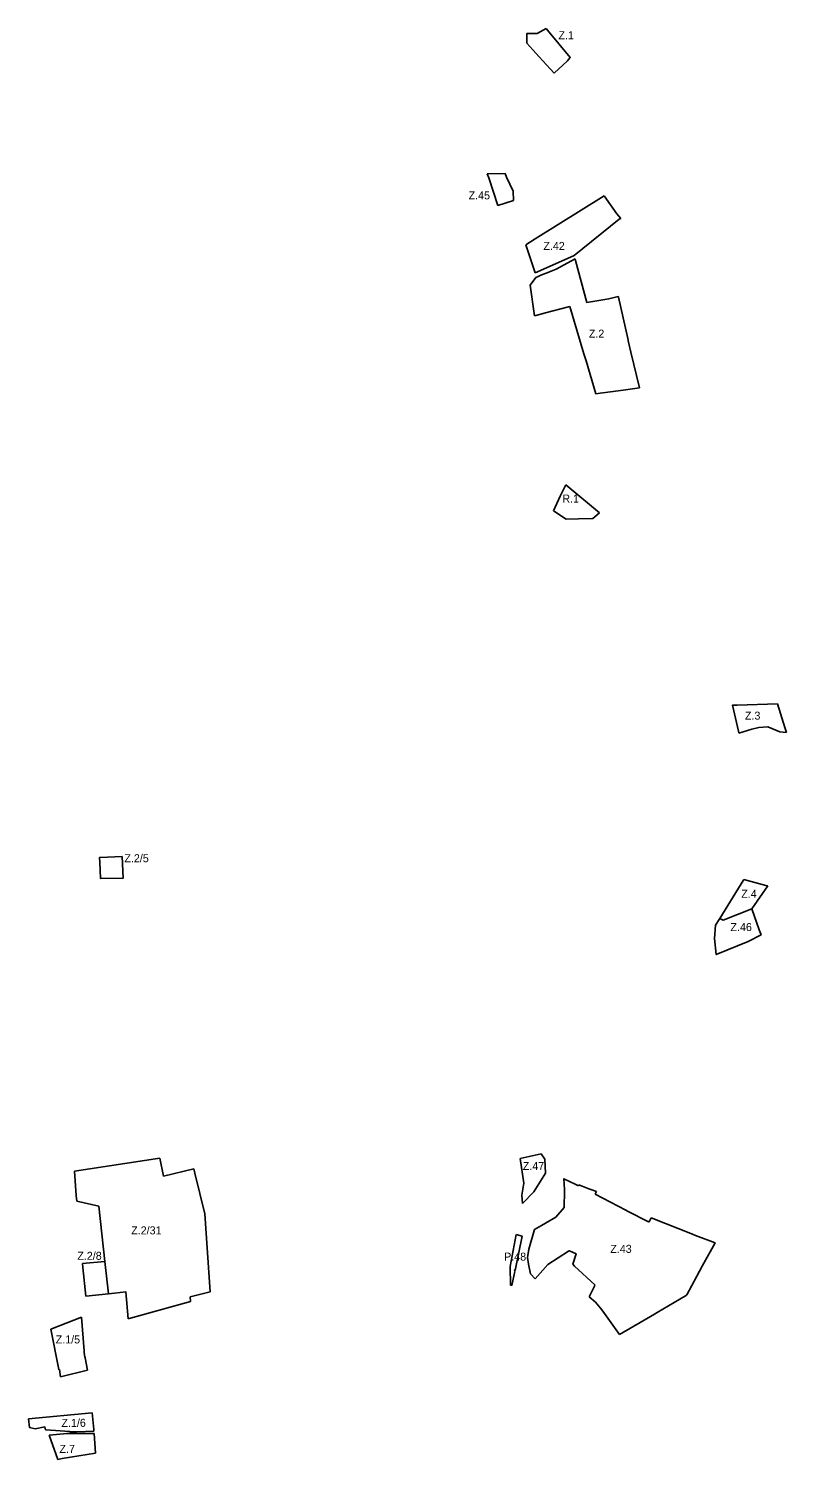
# Model space of a CAD drawing. Extents: x -438701 to -435614, y -1126017 to -1121766.
# Drawn here: x -438045 to -437098, y -1123554 to -1121766 of the extents above; entities that cross this region are included whole.
import ezdxf

# ---------------------------------------------------------------- set-up
doc = ezdxf.new("R2010")
doc.units = 0
for name, color, linetype in [('NAVRH', 7, 'Continuous'), ('STAV', 7, 'Continuous'), ('Vrstva 12', 7, 'Continuous'), ('Vrstva 13', 7, 'Continuous'), ('Vrstva 3', 7, 'Continuous'), ('Vrstva 5', 7, 'Continuous'), ('Vrstva 6', 7, 'Continuous'), ('Vrstva 7', 7, 'Continuous'), ('Vrstva 9', 7, 'Continuous')]:
    doc.layers.add(name, color=color, linetype=linetype)

msp = doc.modelspace()

# ---------------------------------------------------------------- linework, layer by layer
at = {"layer": 'NAVRH'}
for p, q in [((-437396.6, -1121767.7), (-437398, -1121765.9)), ((-437414.7, -1121792.6), (-437406.9, -1121801.2)), ((-437406.9, -1121801.2), (-437393.3, -1121816.2)), ((-437388.2, -1121821.8), (-437371.6, -1121806.2)), ((-437371.6, -1121806.2), (-437370.3, -1121804.6)), ((-437393.3, -1121816.2), (-437388.2, -1121821.8)), ((-437449.6, -1121947), (-437471.7, -1121947.3)), ((-437471.7, -1121947.3), (-437470, -1121952.2)), ((-437447.7, -1121951.4), (-437449.6, -1121947)), ((-437439.6, -1121969), (-437447.7, -1121951.4)), ((-437439.1, -1121980.9), (-437439.6, -1121969)), ((-437325.7, -1121974.7), (-437411.8, -1122028.6)), ((-437310, -1121997.2), (-437325.7, -1121974.7)), ((-437363.3, -1122049.6), (-437306.8, -1122004.2)), ((-437305, -1122003.2), (-437310, -1121997.2)), ((-437306.8, -1122004.2), (-437305, -1122003.2)), ((-437411.8, -1122028.6), (-437423.7, -1122036.3)), ((-437423.7, -1122036.3), (-437411.9, -1122071)), ((-437409.1, -1122069.8), (-437363.3, -1122049.6)), ((-437362, -1122053.5), (-437385.7, -1122066.5)), ((-437361.4, -1122055.6), (-437362, -1122053.5)), ((-437347.6, -1122108), (-437361.4, -1122055.6)), ((-437411.3, -1122077), (-437418, -1122086.6)), ((-437411.9, -1122071), (-437409.1, -1122069.8)), ((-437409.1, -1122076), (-437411.3, -1122077)), ((-437404.8, -1122074), (-437409.1, -1122076)), ((-437418, -1122086.6), (-437412.6, -1122124.7)), ((-437400.6, -1122121.5), (-437368.7, -1122113)), ((-437368.7, -1122113), (-437351, -1122172.5)), ((-437320, -1122103.7), (-437347.6, -1122108)), ((-437308.1, -1122100.5), (-437320, -1122103.7)), ((-437307.8, -1122101.4), (-437308.1, -1122100.5)), ((-437296.3, -1122153.1), (-437307.8, -1122101.4)), ((-437412.6, -1122124.7), (-437404.9, -1122122.6)), ((-437404.9, -1122122.6), (-437400.6, -1122121.5)), ((-437295.3, -1122157.7), (-437296.3, -1122153.1)), ((-437292.4, -1122170.4), (-437295.3, -1122157.7)), ((-437281.8, -1122215), (-437292.4, -1122170.4)), ((-437351, -1122172.5), (-437349.6, -1122177.3)), ((-437349.6, -1122177.3), (-437348.4, -1122181.1)), ((-437348.4, -1122181.1), (-437336.1, -1122222.1)), ((-437336.1, -1122222.1), (-437330.8, -1122221.4)), ((-437330.8, -1122221.4), (-437314.6, -1122219.3)), ((-437314.6, -1122219.3), (-437298.9, -1122217.2)), ((-437298.9, -1122217.2), (-437284.7, -1122215.3)), ((-437284.7, -1122215.3), (-437281.8, -1122215)), ((-437109.4, -1122609.8), (-437159.8, -1122611.3)), ((-437099.9, -1122639.3), (-437109.4, -1122609.8)), ((-437158, -1122643.9), (-437157.4, -1122646.2)), ((-437157.4, -1122646.2), (-437141.4, -1122641.3)), ((-437141.4, -1122641.3), (-437132.5, -1122639.1)), ((-437132.5, -1122639.1), (-437121.2, -1122638.5)), ((-437121.2, -1122638.5), (-437106.1, -1122644.8)), ((-437106.1, -1122644.8), (-437098.1, -1122645.4)), ((-437098.1, -1122645.4), (-437099.9, -1122639.3)), ((-437151.1, -1122829.1), (-437181.3, -1122877.7)), ((-437123.7, -1122836.8), (-437151.1, -1122829.1)), ((-437141.4, -1122865.8), (-437121.4, -1122837.2)), ((-437121.4, -1122837.2), (-437123.7, -1122836.8)), ((-437132, -1122892.2), (-437141.4, -1122865.8)), ((-437181.3, -1122877.7), (-437186.6, -1122886.2)), ((-437404.3, -1123171.9), (-437430.5, -1123177.6)), ((-437399.7, -1123178.7), (-437404.3, -1123171.9)), ((-437881, -1123177.2), (-437987.6, -1123193.6)), ((-437876.1, -1123200), (-437881, -1123177.2)), ((-437430.5, -1123177.6), (-437426, -1123208.7)), ((-437399, -1123196.1), (-437399.7, -1123178.7)), ((-437987.6, -1123193.6), (-437985.2, -1123224.1)), ((-437838.2, -1123190.7), (-437876.1, -1123200)), ((-437836.9, -1123196.1), (-437838.2, -1123190.7)), ((-437824.4, -1123247.1), (-437836.9, -1123196.1)), ((-437985.2, -1123224.1), (-437984.6, -1123231)), ((-437426, -1123208.7), (-437428.8, -1123223.5)), ((-437428.8, -1123223.5), (-437427.9, -1123234.2)), ((-437375.1, -1123218.2), (-437375.7, -1123239)), ((-437375.2, -1123216.8), (-437375.1, -1123218.2)), ((-437357.9, -1123212), (-437361.9, -1123210)), ((-437357.5, -1123210.9), (-437357.9, -1123212)), ((-437335.4, -1123219.1), (-437342.2, -1123216.6)), ((-437336.8, -1123222.5), (-437335.4, -1123219.1)), ((-437298.6, -1123242.4), (-437336.8, -1123222.5)), ((-437984.6, -1123231), (-437957.1, -1123237.3)), ((-437957.1, -1123237.3), (-437949.6, -1123306.5)), ((-437375.7, -1123239), (-437386.1, -1123251.2)), ((-437296.7, -1123243.4), (-437298.6, -1123242.4)), ((-437398.9, -1123258.5), (-437404.2, -1123261.5)), ((-437386.1, -1123251.2), (-437398.9, -1123258.5)), ((-437215.3, -1123272.2), (-437267.2, -1123251.9)), ((-437211.7, -1123274), (-437215.3, -1123272.2)), ((-437419.8, -1123291.2), (-437421.2, -1123298.8)), ((-437396.3, -1123310.4), (-437370.2, -1123293.4)), ((-437370.2, -1123293.4), (-437369.3, -1123292.8)), ((-437949.6, -1123306.5), (-437977.3, -1123309)), ((-437977.3, -1123309), (-437976.9, -1123313.8)), ((-437976.9, -1123313.8), (-437973.4, -1123349.8)), ((-437949.6, -1123306.5), (-437945.1, -1123346.9)), ((-437945.1, -1123346.9), (-437949.6, -1123306.5)), ((-437412, -1123328), (-437396.3, -1123310.4)), ((-437210, -1123325), (-437203.2, -1123312.5)), ((-437417.8, -1123321.7), (-437412, -1123328)), ((-437222.6, -1123348.1), (-437210, -1123325)), ((-437973.4, -1123349.8), (-437945.1, -1123346.9)), ((-437945.1, -1123346.9), (-437937.4, -1123346.1)), ((-437842.3, -1123356.3), (-437842.9, -1123350.8)), ((-437344.4, -1123350.8), (-437336.5, -1123357.5)), ((-437259.5, -1123370.3), (-437224, -1123349.5)), ((-437336.5, -1123357.5), (-437330.2, -1123364.8)), ((-437330.2, -1123364.8), (-437327.6, -1123368.5)), ((-437327.6, -1123368.5), (-437306.4, -1123397.8)), ((-437978.6, -1123376.1), (-438017, -1123391)), ((-437975.4, -1123418), (-437978.6, -1123376.1)), ((-437306.4, -1123397.8), (-437262.9, -1123372.3)), ((-437262.9, -1123372.3), (-437259.5, -1123370.3)), ((-438006.9, -1123441.8), (-438006.3, -1123441.6)), ((-438006.3, -1123441.6), (-438004.9, -1123450.7)), ((-438004.9, -1123450.7), (-437971.2, -1123442.3)), ((-437965.5, -1123495.4), (-438044.7, -1123503)), ((-437963.4, -1123516.5), (-437965.5, -1123495.4)), ((-438036.4, -1123515.5), (-438024.5, -1123513.1)), ((-438024.5, -1123513.1), (-438023.8, -1123516.9)), ((-438023.8, -1123516.9), (-438011.2, -1123517.8)), ((-438010, -1123522.6), (-438019.2, -1123523.4)), ((-438019.2, -1123523.4), (-438008.1, -1123553.8)), ((-438009.9, -1123522.6), (-438010, -1123522.6)), ((-437963.2, -1123518.4), (-437963.4, -1123516.5)), ((-437961.3, -1123545.8), (-437962.9, -1123521.5)), ((-438002.6, -1123552.8), (-437961.3, -1123545.8)), ((-438008.1, -1123553.8), (-438002.6, -1123552.8))]:
    msp.add_line(p, q, dxfattribs=at)
for points in [[(-437398, -1121765.9), (-437409.5, -1121772), (-437422.3, -1121772), (-437422.2, -1121784.1), (-437414.7, -1121792.6)], [(-437370.3, -1121804.6), (-437368.4, -1121802.1), (-437396.6, -1121767.7)], [(-437470, -1121952.2), (-437458.5, -1121986.8), (-437439.1, -1121980.9)], [(-437385.7, -1122066.5), (-437394.2, -1122069.9), (-437394.9, -1122070.1), (-437404.8, -1122074)], [(-437159.8, -1122611.3), (-437165.5, -1122611.5), (-437158, -1122643.9)], [(-437955.8, -1122807.7), (-437954.8, -1122828.1), (-437926.7, -1122827.6), (-437928, -1122800.5), (-437946, -1122801.1), (-437956, -1122801.5), (-437955.8, -1122807.7)], [(-437181.3, -1122877.7), (-437176.9, -1122879.8), (-437141.4, -1122865.8)], [(-437141.4, -1122865.8), (-437176.9, -1122879.8), (-437181.3, -1122877.7)], [(-437186.6, -1122886.2), (-437188.1, -1122902.7), (-437185.7, -1122923), (-437145.7, -1122906.7), (-437129.8, -1122898.3), (-437132, -1122892.2)], [(-437427.9, -1123234.2), (-437413.6, -1123219.4), (-437399, -1123196.1)], [(-437361.9, -1123210), (-437376, -1123203.1), (-437375.2, -1123216.5), (-437375.2, -1123216.8)], [(-437342.2, -1123216.6), (-437344.7, -1123215.7), (-437357.5, -1123210.9)], [(-437267.2, -1123251.9), (-437269.4, -1123256.8), (-437270.1, -1123256.4), (-437270.5, -1123257.1), (-437296.7, -1123243.4)], [(-437842.9, -1123350.8), (-437818, -1123344.4), (-437824.4, -1123247.1)], [(-437404.2, -1123261.5), (-437412.6, -1123266.7), (-437419.8, -1123291.2)], [(-437203.2, -1123312.5), (-437187.2, -1123283.2), (-437211.7, -1123274)], [(-437369.3, -1123292.8), (-437369.1, -1123293.1), (-437360.8, -1123296.9), (-437364.8, -1123310), (-437363, -1123312.5), (-437337.5, -1123335.8)], [(-437421.2, -1123298.8), (-437421.7, -1123301.7), (-437420.2, -1123310), (-437417.8, -1123321.7)], [(-437937.4, -1123346.1), (-437923.1, -1123344.6), (-437920.5, -1123378.3)], [(-437337.5, -1123335.8), (-437338, -1123337.5), (-437344.4, -1123350.8)], [(-437224, -1123349.5), (-437223.2, -1123349), (-437222.6, -1123348.1)], [(-437920.5, -1123378.3), (-437917.5, -1123377.5), (-437842.3, -1123356.3)], [(-438017, -1123391), (-438007, -1123441.4), (-438006.9, -1123441.8)], [(-437971.2, -1123442.3), (-437974.2, -1123427), (-437974.4, -1123425.6), (-437974.9, -1123423.5), (-437975.2, -1123419.8), (-437975.4, -1123418)], [(-438044.7, -1123503), (-438043.7, -1123513.9), (-438036.4, -1123515.5)], [(-438011.2, -1123517.8), (-437993.6, -1123519.1), (-437992.6, -1123519.2), (-437989.7, -1123519.4), (-437984.3, -1123519.5), (-437963.2, -1123518.4)], [(-437962.9, -1123521.5), (-437997, -1123521.5), (-438009.9, -1123522.6)]]:
    msp.add_lwpolyline(points, dxfattribs=at)
at = {"layer": 'Vrstva 3'}
for p, q in [((-437435.5, -1123272.8), (-437443.3, -1123312.9)), ((-437436.7, -1123315.7), (-437428, -1123274.7)), ((-437428, -1123274.7), (-437435.5, -1123272.8)), ((-437443.3, -1123312.9), (-437442.6, -1123336.1)), ((-437441.1, -1123336.5), (-437437.4, -1123319.2)), ((-437437.7, -1123318.7), (-437436.7, -1123315.7)), ((-437437.4, -1123319.2), (-437437.7, -1123318.7)), ((-437442.6, -1123336.1), (-437441.1, -1123336.5))]:
    msp.add_line(p, q, dxfattribs=at)
at = {"layer": 'Vrstva 5'}
for p, q in [((-437380.6, -1122350), (-437373.5, -1122336)), ((-437373.5, -1122336), (-437331.5, -1122371.1)), ((-437388.9, -1122368.4), (-437384.8, -1122359.3)), ((-437384.8, -1122359.3), (-437380.6, -1122350))]:
    msp.add_line(p, q, dxfattribs=at)
msp.add_lwpolyline([(-437331.5, -1122371.1), (-437339.9, -1122378.2), (-437357.8, -1122378.5), (-437373.3, -1122378.8), (-437388.9, -1122368.4)], dxfattribs=at)
at = {"layer": 'Vrstva 6'}
for p, q in [((-437396.6, -1121767.7), (-437398, -1121765.9)), ((-437414.7, -1121792.6), (-437406.9, -1121801.2)), ((-437406.9, -1121801.2), (-437393.3, -1121816.2)), ((-437388.2, -1121821.8), (-437371.6, -1121806.2)), ((-437371.6, -1121806.2), (-437370.3, -1121804.6)), ((-437393.3, -1121816.2), (-437388.2, -1121821.8)), ((-437449.6, -1121947), (-437471.7, -1121947.3)), ((-437471.7, -1121947.3), (-437470, -1121952.2)), ((-437447.7, -1121951.4), (-437449.6, -1121947)), ((-437439.6, -1121969), (-437447.7, -1121951.4)), ((-437439.1, -1121980.9), (-437439.6, -1121969)), ((-437325.7, -1121974.7), (-437411.8, -1122028.6)), ((-437310, -1121997.2), (-437325.7, -1121974.7)), ((-437363.3, -1122049.6), (-437306.8, -1122004.2)), ((-437305, -1122003.2), (-437310, -1121997.2)), ((-437306.8, -1122004.2), (-437305, -1122003.2)), ((-437411.8, -1122028.6), (-437423.7, -1122036.3)), ((-437423.7, -1122036.3), (-437411.9, -1122071)), ((-437409.1, -1122069.8), (-437363.3, -1122049.6)), ((-437362, -1122053.5), (-437385.7, -1122066.5)), ((-437361.4, -1122055.6), (-437362, -1122053.5)), ((-437347.6, -1122108), (-437361.4, -1122055.6)), ((-437411.3, -1122077), (-437418, -1122086.6)), ((-437411.9, -1122071), (-437409.1, -1122069.8)), ((-437409.1, -1122076), (-437411.3, -1122077)), ((-437404.8, -1122074), (-437409.1, -1122076)), ((-437418, -1122086.6), (-437412.6, -1122124.7)), ((-437400.6, -1122121.5), (-437368.7, -1122113)), ((-437368.7, -1122113), (-437351, -1122172.5)), ((-437320, -1122103.7), (-437347.6, -1122108)), ((-437308.1, -1122100.5), (-437320, -1122103.7)), ((-437307.8, -1122101.4), (-437308.1, -1122100.5)), ((-437296.3, -1122153.1), (-437307.8, -1122101.4)), ((-437412.6, -1122124.7), (-437404.9, -1122122.6)), ((-437404.9, -1122122.6), (-437400.6, -1122121.5)), ((-437295.3, -1122157.7), (-437296.3, -1122153.1)), ((-437292.4, -1122170.4), (-437295.3, -1122157.7)), ((-437281.8, -1122215), (-437292.4, -1122170.4)), ((-437351, -1122172.5), (-437349.6, -1122177.3)), ((-437349.6, -1122177.3), (-437348.4, -1122181.1)), ((-437348.4, -1122181.1), (-437336.1, -1122222.1)), ((-437336.1, -1122222.1), (-437330.8, -1122221.4)), ((-437330.8, -1122221.4), (-437314.6, -1122219.3)), ((-437314.6, -1122219.3), (-437298.9, -1122217.2)), ((-437298.9, -1122217.2), (-437284.7, -1122215.3)), ((-437284.7, -1122215.3), (-437281.8, -1122215)), ((-437109.4, -1122609.8), (-437159.8, -1122611.3)), ((-437099.9, -1122639.3), (-437109.4, -1122609.8)), ((-437158, -1122643.9), (-437157.4, -1122646.2)), ((-437157.4, -1122646.2), (-437141.4, -1122641.3)), ((-437141.4, -1122641.3), (-437132.5, -1122639.1)), ((-437132.5, -1122639.1), (-437121.2, -1122638.5)), ((-437121.2, -1122638.5), (-437106.1, -1122644.8)), ((-437106.1, -1122644.8), (-437098.1, -1122645.4)), ((-437098.1, -1122645.4), (-437099.9, -1122639.3)), ((-437151.1, -1122829.1), (-437181.3, -1122877.7)), ((-437123.7, -1122836.8), (-437151.1, -1122829.1)), ((-437141.4, -1122865.8), (-437121.4, -1122837.2)), ((-437121.4, -1122837.2), (-437123.7, -1122836.8)), ((-437141.4, -1122865.8), (-437176.9, -1122879.8)), ((-437176.9, -1122879.8), (-437141.4, -1122865.8)), ((-437132, -1122892.2), (-437141.4, -1122865.8)), ((-437181.3, -1122877.7), (-437186.6, -1122886.2)), ((-437176.9, -1122879.8), (-437181.3, -1122877.7)), ((-437181.3, -1122877.7), (-437176.9, -1122879.8)), ((-437404.3, -1123171.9), (-437430.5, -1123177.6)), ((-437399.7, -1123178.7), (-437404.3, -1123171.9)), ((-437881, -1123177.2), (-437987.6, -1123193.6)), ((-437876.1, -1123200), (-437881, -1123177.2)), ((-437430.5, -1123177.6), (-437426, -1123208.7)), ((-437399, -1123196.1), (-437399.7, -1123178.7)), ((-437987.6, -1123193.6), (-437985.2, -1123224.1)), ((-437838.2, -1123190.7), (-437876.1, -1123200)), ((-437836.9, -1123196.1), (-437838.2, -1123190.7)), ((-437824.4, -1123247.1), (-437836.9, -1123196.1)), ((-437985.2, -1123224.1), (-437984.6, -1123231)), ((-437426, -1123208.7), (-437428.8, -1123223.5)), ((-437428.8, -1123223.5), (-437427.9, -1123234.2)), ((-437375.1, -1123218.2), (-437375.7, -1123239)), ((-437375.2, -1123216.8), (-437375.1, -1123218.2)), ((-437357.9, -1123212), (-437361.9, -1123210)), ((-437357.5, -1123210.9), (-437357.9, -1123212)), ((-437335.4, -1123219.1), (-437342.2, -1123216.6)), ((-437336.8, -1123222.5), (-437335.4, -1123219.1)), ((-437298.6, -1123242.4), (-437336.8, -1123222.5)), ((-437984.6, -1123231), (-437957.1, -1123237.3)), ((-437957.1, -1123237.3), (-437949.6, -1123306.5)), ((-437375.7, -1123239), (-437386.1, -1123251.2)), ((-437296.7, -1123243.4), (-437298.6, -1123242.4)), ((-437398.9, -1123258.5), (-437404.2, -1123261.5)), ((-437386.1, -1123251.2), (-437398.9, -1123258.5)), ((-437215.3, -1123272.2), (-437267.2, -1123251.9)), ((-437211.7, -1123274), (-437215.3, -1123272.2)), ((-437419.8, -1123291.2), (-437421.2, -1123298.8)), ((-437396.3, -1123310.4), (-437370.2, -1123293.4)), ((-437370.2, -1123293.4), (-437369.3, -1123292.8)), ((-437949.6, -1123306.5), (-437977.3, -1123309)), ((-437977.3, -1123309), (-437976.9, -1123313.8)), ((-437976.9, -1123313.8), (-437973.4, -1123349.8)), ((-437949.6, -1123306.5), (-437945.1, -1123346.9)), ((-437945.1, -1123346.9), (-437949.6, -1123306.5)), ((-437412, -1123328), (-437396.3, -1123310.4)), ((-437210, -1123325), (-437203.2, -1123312.5)), ((-437417.8, -1123321.7), (-437412, -1123328)), ((-437222.6, -1123348.1), (-437210, -1123325)), ((-437973.4, -1123349.8), (-437945.1, -1123346.9)), ((-437945.1, -1123346.9), (-437937.4, -1123346.1)), ((-437842.3, -1123356.3), (-437842.9, -1123350.8)), ((-437344.4, -1123350.8), (-437336.5, -1123357.5)), ((-437259.5, -1123370.3), (-437224, -1123349.5)), ((-437336.5, -1123357.5), (-437330.2, -1123364.8)), ((-437330.2, -1123364.8), (-437327.6, -1123368.5)), ((-437327.6, -1123368.5), (-437306.4, -1123397.8)), ((-437978.6, -1123376.1), (-438017, -1123391)), ((-437975.4, -1123418), (-437978.6, -1123376.1)), ((-437306.4, -1123397.8), (-437262.9, -1123372.3)), ((-437262.9, -1123372.3), (-437259.5, -1123370.3)), ((-438006.9, -1123441.8), (-438006.3, -1123441.6)), ((-438006.3, -1123441.6), (-438004.9, -1123450.7)), ((-438004.9, -1123450.7), (-437971.2, -1123442.3)), ((-437965.5, -1123495.4), (-438044.7, -1123503)), ((-437963.4, -1123516.5), (-437965.5, -1123495.4)), ((-438036.4, -1123515.5), (-438024.5, -1123513.1)), ((-438024.5, -1123513.1), (-438023.8, -1123516.9)), ((-438023.8, -1123516.9), (-438011.2, -1123517.8)), ((-438010, -1123522.6), (-438019.2, -1123523.4)), ((-438019.2, -1123523.4), (-438008.1, -1123553.8)), ((-438009.9, -1123522.6), (-438010, -1123522.6)), ((-437963.2, -1123518.4), (-437963.4, -1123516.5)), ((-437961.3, -1123545.8), (-437962.9, -1123521.5)), ((-438002.6, -1123552.8), (-437961.3, -1123545.8)), ((-438008.1, -1123553.8), (-438002.6, -1123552.8))]:
    msp.add_line(p, q, dxfattribs=at)
for points in [[(-437398, -1121765.9), (-437409.5, -1121772), (-437422.3, -1121772), (-437422.2, -1121784.1), (-437414.7, -1121792.6)], [(-437370.3, -1121804.6), (-437368.4, -1121802.1), (-437396.6, -1121767.7)], [(-437470, -1121952.2), (-437458.5, -1121986.8), (-437439.1, -1121980.9)], [(-437385.7, -1122066.5), (-437394.2, -1122069.9), (-437394.9, -1122070.1), (-437404.8, -1122074)], [(-437159.8, -1122611.3), (-437165.5, -1122611.5), (-437158, -1122643.9)], [(-437955.8, -1122807.7), (-437954.8, -1122828.1), (-437926.7, -1122827.6), (-437928, -1122800.5), (-437946, -1122801.1), (-437956, -1122801.5), (-437955.8, -1122807.7)], [(-437186.6, -1122886.2), (-437188.1, -1122902.7), (-437185.7, -1122923), (-437145.7, -1122906.7), (-437129.8, -1122898.3), (-437132, -1122892.2)], [(-437427.9, -1123234.2), (-437413.6, -1123219.4), (-437399, -1123196.1)], [(-437361.9, -1123210), (-437376, -1123203.1), (-437375.2, -1123216.5), (-437375.2, -1123216.8)], [(-437342.2, -1123216.6), (-437344.7, -1123215.7), (-437357.5, -1123210.9)], [(-437267.2, -1123251.9), (-437269.4, -1123256.8), (-437270.1, -1123256.4), (-437270.5, -1123257.1), (-437296.7, -1123243.4)], [(-437842.9, -1123350.8), (-437818, -1123344.4), (-437824.4, -1123247.1)], [(-437404.2, -1123261.5), (-437412.6, -1123266.7), (-437419.8, -1123291.2)], [(-437203.2, -1123312.5), (-437187.2, -1123283.2), (-437211.7, -1123274)], [(-437369.3, -1123292.8), (-437369.1, -1123293.1), (-437360.8, -1123296.9), (-437364.8, -1123310), (-437363, -1123312.5), (-437337.5, -1123335.8)], [(-437421.2, -1123298.8), (-437421.7, -1123301.7), (-437420.2, -1123310), (-437417.8, -1123321.7)], [(-437937.4, -1123346.1), (-437923.1, -1123344.6), (-437920.5, -1123378.3)], [(-437337.5, -1123335.8), (-437338, -1123337.5), (-437344.4, -1123350.8)], [(-437224, -1123349.5), (-437223.2, -1123349), (-437222.6, -1123348.1)], [(-437920.5, -1123378.3), (-437917.5, -1123377.5), (-437842.3, -1123356.3)], [(-438017, -1123391), (-438007, -1123441.4), (-438006.9, -1123441.8)], [(-437971.2, -1123442.3), (-437974.2, -1123427), (-437974.4, -1123425.6), (-437974.9, -1123423.5), (-437975.2, -1123419.8), (-437975.4, -1123418)], [(-438044.7, -1123503), (-438043.7, -1123513.9), (-438036.4, -1123515.5)], [(-438011.2, -1123517.8), (-437993.6, -1123519.1), (-437992.6, -1123519.2), (-437989.7, -1123519.4), (-437984.3, -1123519.5), (-437963.2, -1123518.4)], [(-437962.9, -1123521.5), (-437997, -1123521.5), (-438009.9, -1123522.6)]]:
    msp.add_lwpolyline(points, dxfattribs=at)
at = {"layer": 'Vrstva 7'}
for p, q in [((-437435.5, -1123272.8), (-437443.3, -1123312.9)), ((-437436.7, -1123315.7), (-437428, -1123274.7)), ((-437428, -1123274.7), (-437435.5, -1123272.8)), ((-437443.3, -1123312.9), (-437442.6, -1123336.1)), ((-437441.1, -1123336.5), (-437437.4, -1123319.2)), ((-437437.7, -1123318.7), (-437436.7, -1123315.7)), ((-437437.4, -1123319.2), (-437437.7, -1123318.7)), ((-437442.6, -1123336.1), (-437441.1, -1123336.5))]:
    msp.add_line(p, q, dxfattribs=at)

# ---------------------------------------------------------------- texts
at = {"layer": 'STAV'}
msp.add_text('P.48', height=10, dxfattribs=at).set_placement((-437450.7, -1123305.4))
at = {"layer": 'Vrstva 12'}
msp.add_text('R.1', height=10, dxfattribs=at).set_placement((-437378, -1122358.2))
at = {"layer": 'Vrstva 13'}
msp.add_text('R.1', height=10, dxfattribs=at).set_placement((-437378, -1122358.2))
at = {"layer": 'Vrstva 9'}
for s, p in [('Z.1', (-437382.8, -1121779.2)), ('Z.45', (-437495.1, -1121979.3)), ('Z.42', (-437401.7, -1122042.5)), ('Z.2', (-437344.9, -1122152.1)), ('Z.3', (-437149.9, -1122629.4)), ('Z.2/5', (-437925.1, -1122807.6)), ('Z.4', (-437154.5, -1122852)), ('Z.46', (-437168, -1122893.6)), ('Z.47', (-437427.4, -1123192.2)), ('Z.2/31', (-437916.6, -1123272.6)), ('Z.2/8', (-437983.9, -1123304.4)), ('Z.43', (-437318.1, -1123295.7)), ('Z.1/5', (-438010.9, -1123408.9)), ('Z.1/6', (-438003.7, -1123513.1)), ('Z.7', (-438006.2, -1123545.7))]:
    msp.add_text(s, height=10, dxfattribs=at).set_placement(p)

doc.saveas('drawing.dxf')
